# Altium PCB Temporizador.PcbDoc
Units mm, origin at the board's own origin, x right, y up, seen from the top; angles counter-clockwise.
Board outline 120.65 x 55.24 mm, 2 copper layers (Top Layer, Bottom Layer); 47 components, 35 nets, 161 pads, 9 vias.
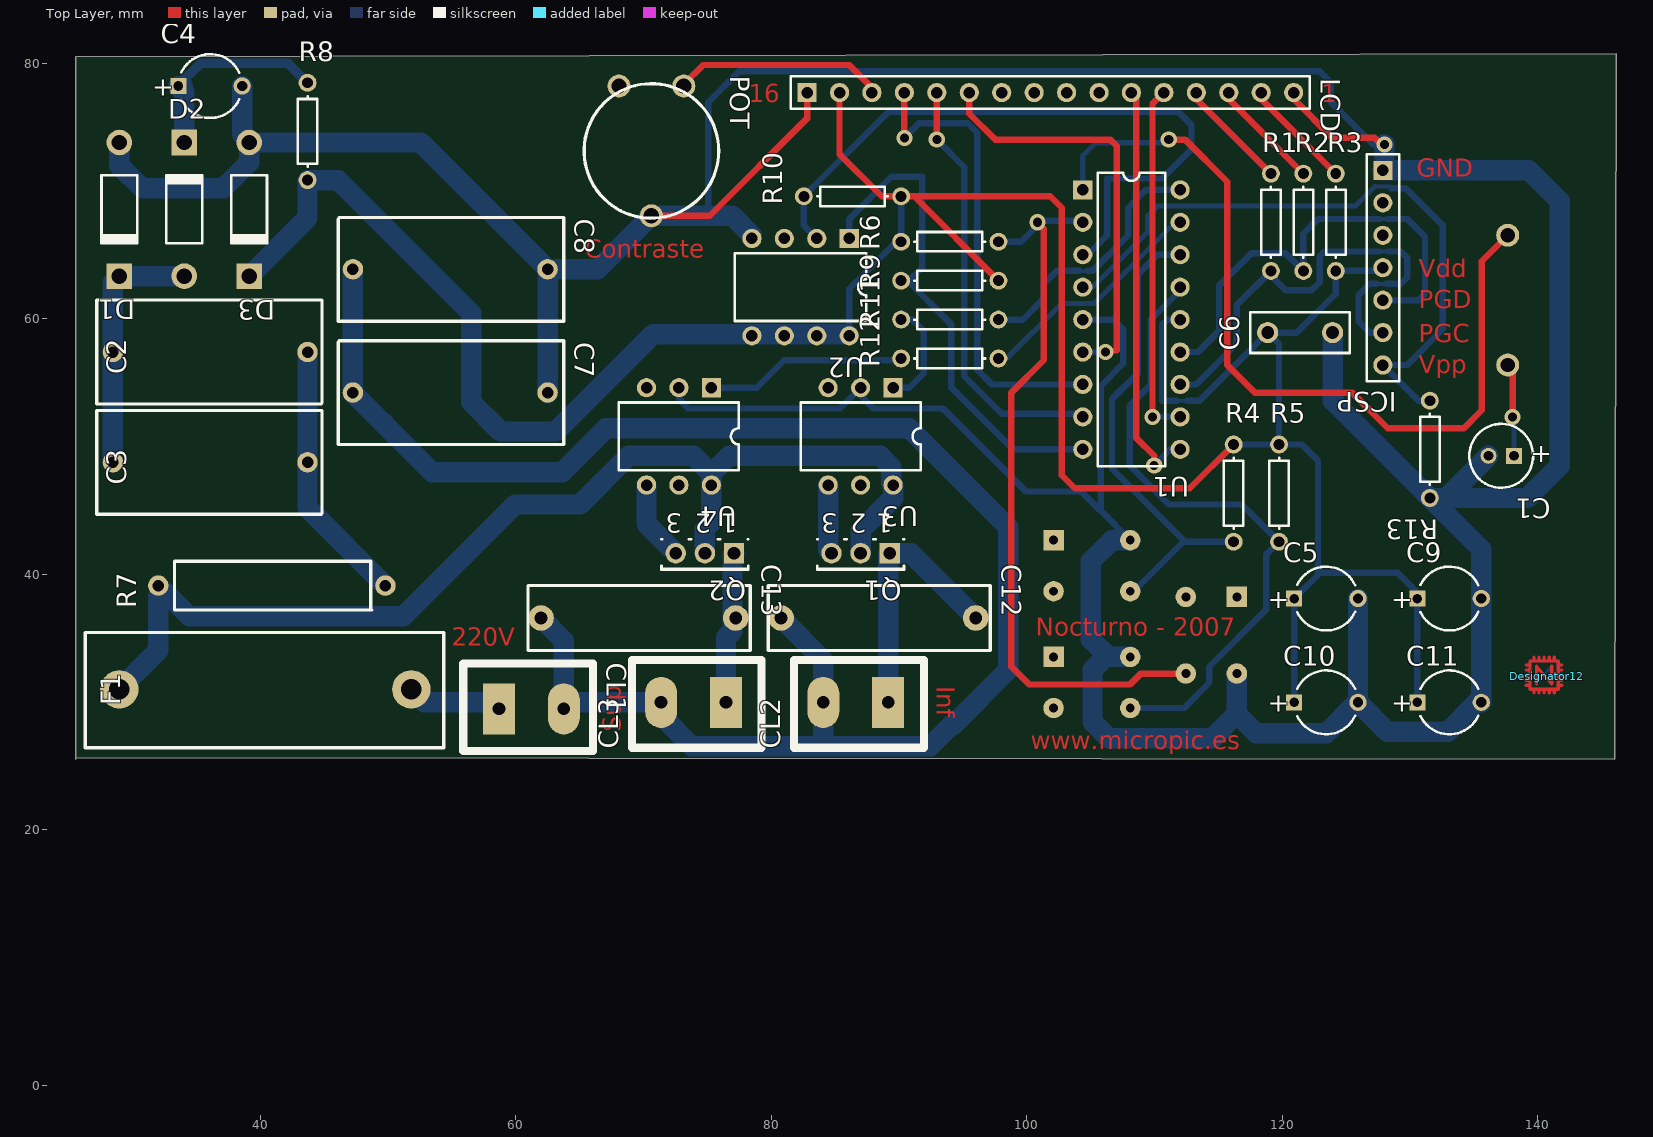
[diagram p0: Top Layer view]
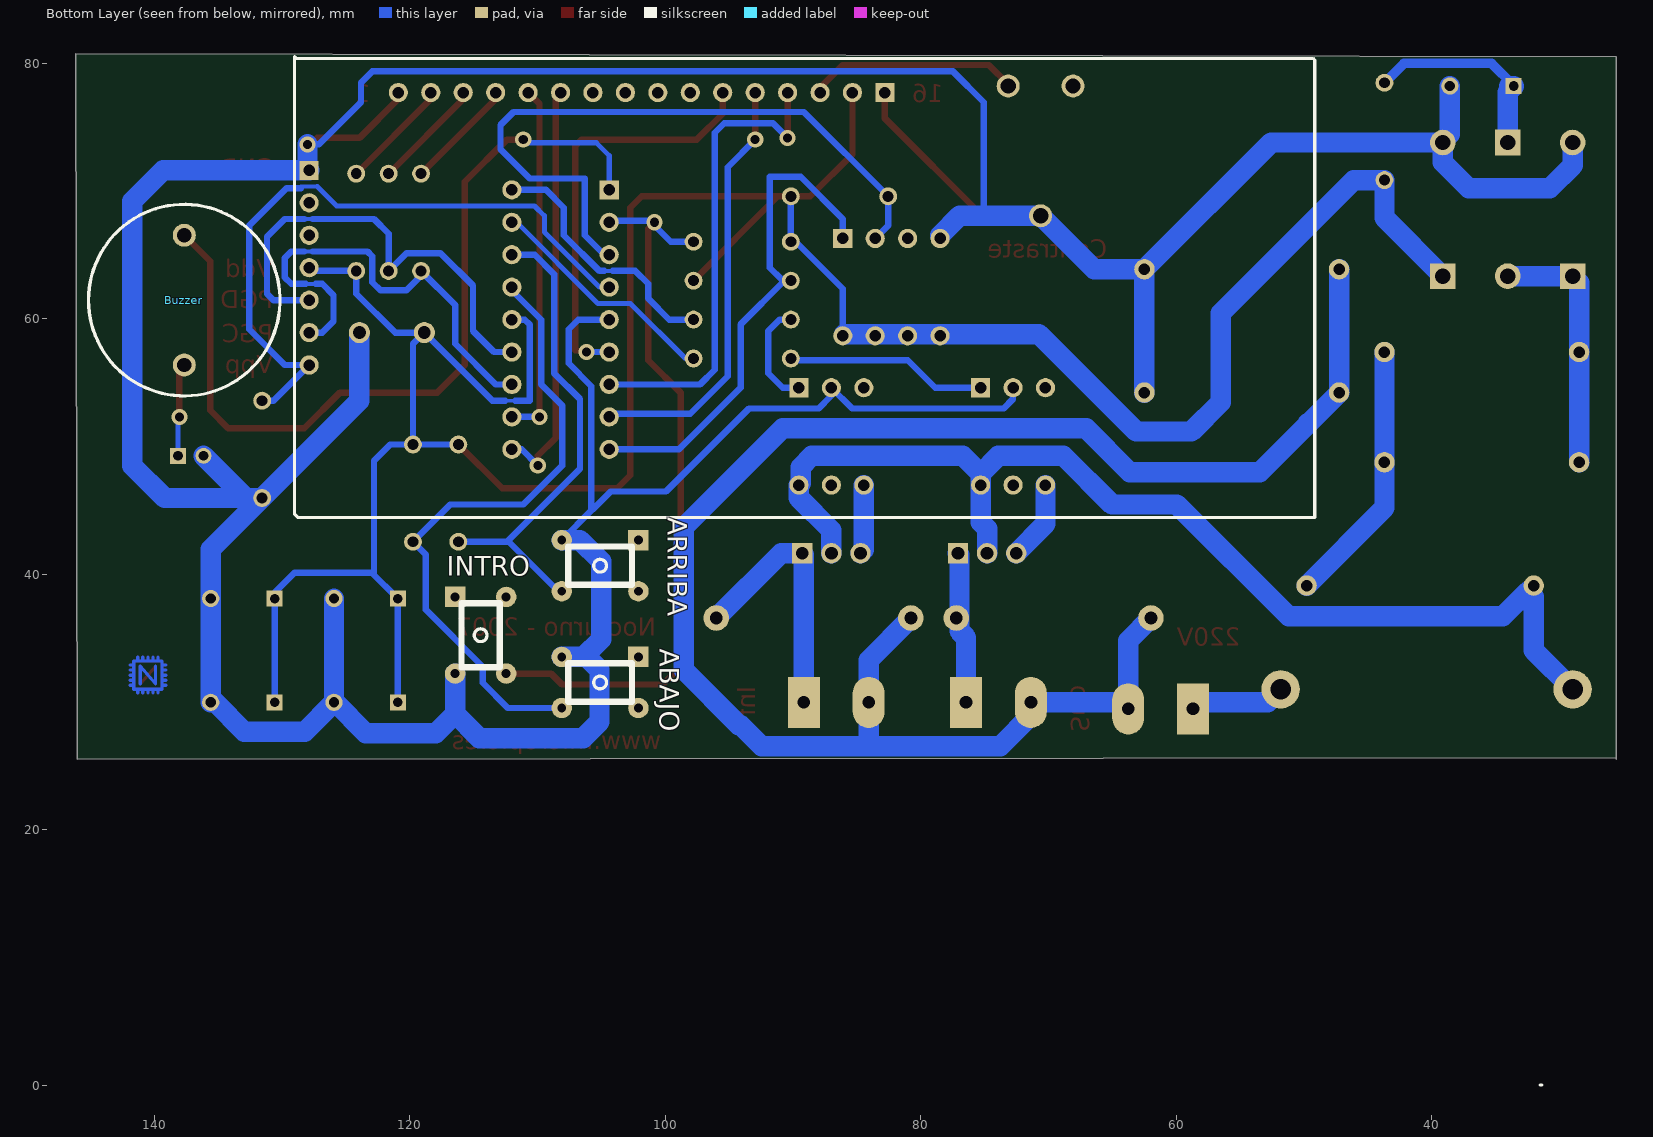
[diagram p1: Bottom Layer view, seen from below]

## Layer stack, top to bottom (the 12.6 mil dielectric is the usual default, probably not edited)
Top Layer: signal copper 0.0356
Dielectric: dielectric 0.32, FR-4, Dk 4.8
Bottom Layer: signal copper 0.0356

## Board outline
25.527,25.527 25.527,80.518 146.177,80.772 146.05,25.527 25.527,25.654

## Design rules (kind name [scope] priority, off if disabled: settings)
Clearance [InNet('220V_NEUTRO')] p1: gap=0.5
ComponentClearance [All] p1: gap=0.254 collisioncheckmode=3 verticalgap=0.254
PolygonConnect [All] p1: connectstyle=Relief reliefconductorwidth=0.254 reliefentries=4 polygonreliefangle="90 Angle"
RoutingLayers [All] p1: top layer_v5=FALSE bottom layer_v5=TRUE
RoutingVias [All] p1: holewidth=0.711 width=1.27 viastyle="Through Hole" minholewidth=0.711 minwidth=1.27 maxholewidth=0.711 maxwidth=1.27
SolderMaskExpansion [All] p1: expansion=0.102
TestPointUsage [All] p1: valid=0 allowmultiple=FALSE
Testpoint [All] p1: side=15 testpointundercomponent=TRUE minsize=1.016 maxsize=2.54 preferedsize=1.524 minholesize=0 maxholesize=1.016 preferedholesize=0.813 testpointgrid=0.025 style=1023 order=0123456789
Width [All] p1: maxlimit=1.6 minlimit=0.254 preferedwidth=0.254 toplayer_minwidth=0.5 toplayer_maxwidth=0.5 toplayer_prefwidth=0.5 bottomlayer_minwidth=0.3 bottomlayer_prefwidth=1.6 minimp=50.000000 maximp=50.000000 favimp=50.000000
17 further rules are at their usual default settings.

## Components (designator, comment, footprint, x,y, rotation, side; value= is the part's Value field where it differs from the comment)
ABAJO "SW-PB" pulsador 102.108,33.528 r270 bottom
ARRIBA "SW-PB" pulsador 102.108,42.672 r270 bottom
Buzzer "Buzzer" BUZZER 137.668,58.928 r90 bottom
C1 "Cap Pol1" B 137.16,49.276 r180 top
C2 "Cap" RAD-5 36.068,57.404 r180 top
C3 "Cap" RAD-5 36.068,48.768 r180 top
C4 "Cap Pol1" CAPPR5-5x5 36.068,78.232 r0 top
C5 "Cap Pol1" CAPPR5-5x5 123.444,38.1 r0 top
C6 "Cap" VP45-3.2 121.412,58.928 r180 top
C7 "Cap" RAD-5 54.864,54.229 r0 top
C8 "Cap" RAD-5 54.864,63.881 r0 top
C9 "Cap Pol1" CAPPR5-5x5 133.096,38.1 r0 top
C10 "Cap Pol1" CAPPR5-5x5 123.444,29.972 r0 top
C11 "Cap Pol1" CAPPR5-5x5 133.096,29.972 r0 top
C12 "Cap" COND56K 88.392,36.576 r0 top
C13 "Cap" COND56K 69.596,36.576 r0 top
CL1 "220V" Clema-2 54.864,29.464 r0 top
CL2 "Cara inferior" Clema-2 92.964,29.972 r180 top
CL3 "Cara superior" Clema-2 80.264,29.972 r180 top
D1 "Diode 1N4007" DO-41 28.956,68.58 r270 top
D2 "Diode 1N4007" DO-41 34.036,68.58 r90 top
D3 "5V1" do-41 39.116,68.58 r270 top
Designator12 "Comment" Firma 140.716,32.004 r0 top
F1 "Fuse 2" FUSE 36.576,30.988 r180 top
ICSP "Header 7" HDR1X7 127.889,71.628 r270 top
INTRO "SW-PB" pulsador 116.459,38.227 r180 bottom
LCD "Header 16" HDR1X16 82.804,77.724 r0 top
POT "RPot" POTENCIOMETRO 70.612,75.692 r270 top
Q1 "Triac" 369-03 86.995,41.656 r180 top
Q2 "Triac" 369-03 74.803,41.656 r180 top
R1 "Res1" AXIAL-0.3 119.126,67.564 r90 top
R2 "Res1" AXIAL-0.3 121.666,67.564 r90 top
R3 "Res1" AXIAL-0.3 124.206,67.564 r90 top
R4 "Res1" AXIAL-0.3 116.205,46.355 r90 top
R5 "Res1" AXIAL-0.3 119.761,46.355 r90 top
R6 "Res1" AXIAL-0.3 93.98,66.04 r180 top
R7 "Res1" RES1W 42.164,39.116 r180 top
R8 "Res1" AXIAL-0.3 43.688,74.676 r90 top
R9 "Res1" AXIAL-0.3 93.98,62.992 r180 top
R10 "Res1" AXIAL-0.3 86.36,69.596 r180 top
R11 "Res1" AXIAL-0.3 93.98,59.944 r180 top
R12 "Res1" AXIAL-0.3 93.98,56.896 r180 top
R13 "Res1" AXIAL-0.3 131.572,49.784 r270 top
U1 "PIC16F628-04/P" PDIP300-18 108.204,59.944 r270 top
U2 "DS1624" DIP-8 82.296,62.484 r180 top
U3 "Opto TRIAC" DIP-6 86.995,50.8 r180 top
U4 "Opto TRIAC" DIP-6 72.771,50.8 r180 top

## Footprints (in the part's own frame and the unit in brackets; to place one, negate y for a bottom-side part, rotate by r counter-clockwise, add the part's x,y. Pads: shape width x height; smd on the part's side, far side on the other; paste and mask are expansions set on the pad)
369-03 [mm] "TO, Thru-Hole, Vertical, Heatsink Mounted; 3 In-Line Leads; Pitch 2.28 mm"
  rect 1.6x1.6 hole 1: 1(-2.28,0)
  round 1.6 hole 1: 2(0,0) 3(2.28,0)
  silkscreen extent -3.4,-1.1 3.4,1.3
AXIAL-0.3 [mm] "Resistor; 2 Leads"
  round 1.4 hole 0.85: 1(-3.81,0) 2(3.81,0)
  silkscreen extent -2.77,-0.76 2.77,0.76
B [mm] "Capacitor, Electrolytic, Radial; Body 5 x 6.8 mm (Dia.xH typ); Pin Spacing 2 mm (typ)"
  rect 1.25x1.25 hole 0.75: 1(-1,0)
  round 1.25 hole 0.75: 2(1,0)
  silkscreen extent -2.5,-2.5 2.5,2.5
BUZZER [mm]
  round 1.8 hole 1.1: 1(-2.54,0) 2(7.62,0)
  silkscreen extent -4.96,-7.5 10.04,7.5
CAPPR5-5x5 [mm] "Capacitor, Electrolytic, Radial; Body 5 x 5 mm (Dia.xH typ); Pin Spacing 5 mm (typ)"
  rect 1.25x1.25 hole 0.75: 1(-2.5,0)
  round 1.35 hole 0.8: 2(2.5,0)
  silkscreen extent -2.26,-2.5 2.27,2.5
Clema-2 [mm]
  rect 2.5x4 hole 1: 1(3.81,0)
  oval 2.5x4 hole 1: 2(8.89,0)
  silkscreen extent 1.02,-3.3 11.18,3.56
COND56K [mm]
  round 2 hole 1: 1(7.62,0) 2(-7.62,0)
  silkscreen extent -8.64,-2.54 8.76,2.54
DIP-6 [mm] "DIP; 6 Leads; Row Spacing 7.62 mm; Pitch 2.54 mm"
  rect 1.5x1.5 hole 0.9: 1(-2.54,-3.81)
  round 1.5 hole 0.9: 2(0,-3.81) 3(2.54,-3.81) 4(2.54,3.81) 5(0,3.81) 6(-2.54,3.81)
  silkscreen extent -4.7,-2.65 4.7,2.65
DIP-8 [mm]
  rect 1.5x1.5 hole 0.9: 1(-3.81,-3.81)
  round 1.5 hole 0.9: 2(-1.27,-3.81) 3(1.27,-3.81) 4(3.81,-3.81) 5(3.81,3.81) 6(1.27,3.81) 7(-1.27,3.81) 8(-3.81,3.81)
  silkscreen extent -5.15,-2.65 5.15,2.65
DO-41 [mm] "Diode, Axial; Body 5.2 x 2.7 mm (LxDia. max), Lead Dia. 0.86 mm (max)"
  round 2 hole 1.2: 1(-5.23,0)
  rect 2x2 hole 1.2: 2(5.23,0)
  silkscreen extent -2.65,-1.41 2.75,1.4
do-41 [mm] "Diode, Axial; Body 5.2 x 2.7 mm (LxDia. max), Lead Dia. 0.86 mm (max)"
  round 2 hole 1.2: 1(-5.23,0)
  rect 2x2 hole 1.2: 2(5.23,0)
  silkscreen extent -2.65,-1.4 2.75,1.4
Firma [mm] "Firma"
  Top Layer lines w0.254: -1.6,-0.7 -1.3,-0.7 ; -1.6,-0.3 -1.3,-0.3 ; -1.6,0.1 -1.3,0.1 ; -1.6,0.5 -1.3,0.5 ; -1.6,0.9 -1.3,0.9 ; -1,-1.3 -1,-1 ; -1,1.2 -1,1.5 ; -0.8,-0.6 -0.8,0.8 0.4,-0.6 0.4,0.8 ; -0.6,-1.3 -0.6,-1 ; -0.6,1.2 -0.6,1.5 ; -0.2,-1.3 -0.2,-1 ; -0.2,1.2 -0.2,1.5 ; 0.2,-1.3 0.2,-1 ; 0.2,1.2 0.2,1.5 ; 0.6,-1.3 0.6,-1 ; 0.6,1.2 0.6,1.5 ; 0.9,-0.7 1.2,-0.7 ; 0.9,-0.3 1.2,-0.3 ; 0.9,0.1 1.2,0.1 ; 0.9,0.5 1.2,0.5 ; 0.9,0.9 1.2,0.9 ; -1.3,-1 -1.3,1.2 0.9,1.2 0.9,-1 -1.3,-1
  Bottom Layer lines w0.254: -1.6,-0.7 -1.3,-0.7 ; -1.6,-0.3 -1.3,-0.3 ; -1.6,0.1 -1.3,0.1 ; -1.6,0.5 -1.3,0.5 ; -1.6,0.9 -1.3,0.9 ; -1,-1.3 -1,-1 ; -1,1.2 -1,1.5 ; -0.8,0.8 -0.8,-0.6 0.4,0.8 0.4,-0.6 ; -0.6,-1.3 -0.6,-1 ; -0.6,1.2 -0.6,1.5 ; -0.2,-1.3 -0.2,-1 ; -0.2,1.2 -0.2,1.5 ; 0.2,-1.3 0.2,-1 ; 0.2,1.2 0.2,1.5 ; 0.6,-1.3 0.6,-1 ; 0.6,1.2 0.6,1.5 ; 0.9,-0.7 1.2,-0.7 ; 0.9,-0.3 1.2,-0.3 ; 0.9,0.1 1.2,0.1 ; 0.9,0.5 1.2,0.5 ; 0.9,0.9 1.2,0.9 ; -1.3,-1 0.9,-1 0.9,1.2 -1.3,1.2 -1.3,-1
FUSE [mm]
  round 3 hole 1.6: 1(-15.24,0) 2(7.62,0)
  silkscreen extent -17.78,-4.45 10.29,4.57
HDR1X7 [mm] "Connector; Header; 7 Position"
  rect 1.5x1.5 hole 0.9: 1(0,0)
  round 1.5 hole 0.9: 2(2.54,0) 3(5.08,0) 4(7.62,0) 5(10.16,0) 6(12.7,0) 7(15.24,0)
  silkscreen extent -1.27,-1.27 16.51,1.27
HDR1X16 [mm] "Connector; Header; 16 Position"
  rect 1.5x1.5 hole 0.9: 1(0,0)
  round 1.5 hole 0.9: 2(2.54,0) 3(5.08,0) 4(7.62,0) 5(10.16,0) 6(12.7,0) 7(15.24,0) 8(17.78,0) 9(20.32,0) 10(22.86,0) 11(25.4,0) 12(27.94,0) 13(30.48,0) 14(33.02,0) 15(35.56,0) 16(38.1,0)
  silkscreen extent -1.27,-1.27 39.37,1.27
PDIP300-18 [mm] "DIP, Plastic; 18 Leads; Row Spacing 7.62 mm; Pitch 2.54 mm"
  rect 1.5x1.5 hole 0.9: 1(-10.16,-3.81)
  round 1.5 hole 0.9: 2(-7.62,-3.81) 3(-5.08,-3.81) 4(-2.54,-3.81) 5(0,-3.81) 6(2.54,-3.81) 7(5.08,-3.81) 8(7.62,-3.81) 9(10.16,-3.81) 10(10.16,3.81) 11(7.62,3.81) 12(5.08,3.81) 13(2.54,3.81) 14(0,3.81) 15(-2.54,3.81) 16(-5.08,3.81) 17(-7.62,3.81) 18(-10.16,3.81)
  silkscreen extent -11.5,-2.65 11.5,2.65
POTENCIOMETRO [mm]
  round 1.8 hole 1.2: 1(-2.54,2.54) 2(-2.54,-2.54) 3(7.62,0)
  silkscreen extent -2.73,-5.26 7.81,5.27
pulsador [mm] "Pulsador doble circuito"
  rect 1.6x1.6 hole 0.7: 0(0,0)
  round 1.6 hole 0.7: 1(0,-6) 2(4,-6) 3(4,0)
  silkscreen extent 0.5,-5.5 3.5,-0.5
RAD-5 [mm]
  round 1.6 hole 0.9: 1(-7.62,0) 2(7.62,0)
  silkscreen extent -8.76,-4.06 8.89,4.06
RES1W [mm]
  round 1.6 hole 0.9: 1(-7.62,0) 2(10.16,0)
  silkscreen extent -6.55,-1.91 8.89,1.91
VP45-3.2 [mm] "Capacitor, Ceramic, Thru-Hole, Dipped Radial; Body 7.8 x 3.2 mm (WxT) Pin Spacing 5.08 mm (typ)"
  round 1.65 hole 1: 1(-2.54,0) 2(2.54,0)
  silkscreen extent -3.9,-1.6 3.9,1.6

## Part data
ABAJO ARRIBA INTRO: "Switch"
Buzzer: "Magnetic Transducer Buzzer"
C1 C4 C5 C9 C10 C11: "Polarized Capacitor (Radial)"
C2 C3 C6 C7 C8 C12 C13: "Capacitor"
CL1 CL2 CL3: library part Clema-2
D1 D2: "1 Amp General Purpose Rectifier"
D3: library part "D Zener", "Zener Diode"
F1: "Fuse"
ICSP: "Header, 7-Pin"
LCD: "Header, 16-Pin"
POT: "Potentiometer"
Q1 Q2: "Silicon Bidirectional Triode Thyristor"
R1 R2 R3 R4 R5 R6 R7 R8 R9 R10 R11 R12 R13: "Resistor"
U1: "FLASH-Based 8-Bit CMOS Microcontroller, 2K (x14-Bit words) FLASH, 224 Bytes RAM, 4 MHz, 18-Pin PDIP, 3.0 to 5.5V Supply Range, Commercial Temperature"
U3 U4: "Opto-Triac"

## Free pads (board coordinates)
  round 4.6 on Mech1: 0(28.702,41.021) 0(28.702,77.5) 0(140,41.021) 0(140,77.5)
  round 3.1 on Mech1: 0(51,46) 0(51,78) 0(127,46) 0(127,78)
  round 3.5 on Mech1: 0(105.156,31.496) 0(105.156,40.64) 0(114.427,35.306)

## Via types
v1: diameter 1.27, hole 0.711, Top Layer to Bottom Layer, 9 vias

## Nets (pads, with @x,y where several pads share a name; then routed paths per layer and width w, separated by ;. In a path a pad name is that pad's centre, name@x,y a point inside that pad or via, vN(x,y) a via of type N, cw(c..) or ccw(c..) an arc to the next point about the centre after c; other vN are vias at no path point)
220V_FASE: F1.2 Q1.2 Q2.2 R7.2 U3.6 U4.6 | length 87.9
  Bottom Layer w1.6: F1.2 32.004,34.036 32.004,38.227 32.448,38.672 34.417,36.703 51.181,36.703 59.944,45.466 65.024,45.466 68.834,49.276 73.914,49.276 75.311,47.879 ; Q2.2 74.803,43.561 75.311,44.069 75.311,47.879 ; Q1.2 86.995,43.434 89.535,45.974 U3.6 89.408,47.117 89.408,48.387 88.519,49.276 76.708,49.276 75.311,47.879
220V_NEUTRO: C7.1 C8.1 C12.2 C13.2 CL1.2 CL2.2 CL3.2 | length 138.1
  Bottom Layer w1.6: C8.1 C7.1 53.467,48.006 63.627,48.006 67.056,51.435 90.805,51.435 98.552,43.688 98.552,32.512 94.234,28.194 94.107,28.194 92.456,26.543 73.787,26.543 71.247,29.083 71.247,29.845 CL3.2 CL1.2@63.754,29.972 ; 49.679,51.794 49.701,51.816 ; C13.2 63.754,34.798 CL1.2 ; C12.2 84.074,33.274 84.074,26.67 84.201,26.543
GND: ABAJO.1 ARRIBA.1 C1.2 C4.2 C5.2 C6.1 C7.2 C8.2 C9.2 C10.2 C11.2 D1.1 D3.1 ICSP.1 INTRO.1 LCD.1 LCD.16 POT.3 R13.2 U1.5 U2.4 U3.2 U4.2 | length 381.7
  Top Layer w0.5: POT.3 75.184,68.072 82.804,75.692 LCD.1 ; LCD.16 120.904,77.216 123.952,74.168 127.254,74.168 127.762,73.66 v1(128.016,73.66)
  Bottom Layer w0.5: U4.2 72.771,53.721 73.507,52.985 85.37,52.985 U3.2 86.995,53.975 87.985,52.985 93.446,52.985 99.949,46.482 104.267,46.482 105.664,45.085 ; 75.057,68.072 75.057,76.962 77.47,79.375 122.936,79.375 123.825,78.486 123.825,76.962 127.127,73.66 v1(128.016,73.66) ; U1.5 106.807,59.944 107.569,59.182 107.569,56.515 105.791,54.737 105.791,44.989 ARRIBA.1
  Bottom Layer w1.6: D1.1 28.956,72.009 30.734,70.231 37.084,70.231 39.116,72.263 D3.1 ; C4.2 38.568,74.462 38.989,74.041 38.989,73.937 D3.1 ; C7.2 C8.2 ; U2.4@78.486,66.548 76.962,68.072 POT.3 66.421,63.881 C8.2 ; 106.426,33.528 105.029,34.925 105.029,41.021 106.68,42.672 ARRIBA.1 ; ABAJO.1 106.172,33.528 105.156,32.512 105.156,28.448 106.426,27.178 114.554,27.178 116.459,29.083 ; INTRO.1 116.459,29.083 ; C6.1 123.952,53.594 135.596,41.95 C11.2 135.255,29.972 132.969,27.686 128.23,27.686 C10.2 ; C5.2 C10.2 ; v1(128.016,73.66) 128.016,71.755 ICSP.1 139.319,71.628 141.732,69.215 141.732,48.514 139.192,45.974 R13.2 ; 132.858,45.974 C1.2 ; D3.1 52.555,73.81 C8.2 ; 116.459,29.083 117.983,27.559 123.444,27.559 125.857,29.972 C10.2
NetABAJO_2: ABAJO.2 R5.1 U1.15 | length 50.1
  Bottom Layer w0.5: ABAJO.2 112.332,29.528 114.3,31.496 114.3,32.766 118.745,37.211 118.745,41.529 R5.1 116.84,45.466 111.125,45.466 108.077,48.514 108.077,53.213 109.728,54.864 109.728,59.944 112.014,62.23 U1.15
NetARRIBA_2: ARRIBA.2 R4.1 U1.16 | length 37.8
  Bottom Layer w0.5: ARRIBA.2 108.395,38.672 112.268,42.545 R4.1 ; U1.16 110.236,65.024 108.712,63.5 108.712,55.753 106.68,53.721 106.68,48.26 112.395,42.545
NetBuzzer_1: Buzzer.1 C1.1 | length 7.3
  Top Layer w0.5: Buzzer.1 138.049,56.007 v1(138.049,52.324)
  Bottom Layer w0.4: v1(138.049,52.324) 138.16,52.213 C1.1
NetBuzzer_2: Buzzer.2 U1.1 | length 67.3
  Top Layer w0.5: v1(111.125,74.041) 112.395,74.041 115.697,70.739 115.697,56.388 117.856,54.229 125.476,54.229 128.27,51.435 134.239,51.435 135.636,52.832 135.636,64.516 Buzzer.2
  Bottom Layer w0.4: U1.1 104.394,72.771 105.41,73.787 110.871,73.787 v1(111.125,74.041)
NetC2_1: C2.1 C3.1 R7.1 | length 20.8
  Bottom Layer w1.6: C2.1 43.688,45.212 R7.1
NetC2_2: C2.2 C3.2 D1.2 D2.1 | length 19.9
  Bottom Layer w1.6: C3.2 C2.2 28.448,62.842 D1.2 D2.1
NetC4_1: C4.1 D2.2 R8.2 | length 16.5
  Bottom Layer w0.75: C4.1 33.568,78.272 35.306,80.01 42.164,80.01 R8.2
  Bottom Layer w1.6: C4.1@33.909,78.232 C4.1 34.036,77.764 D2.2
NetC12_1: C12.1 CL2.1 Q1.1 | length 20.6
  Bottom Layer w1.6: CL2.1 89.154,41.535 Q1.1 ; Q1.1@89.281,41.65 Q1.1 ; C12.1 90.932,41.656 Q1.1
NetC13_1: C13.1 CL3.1 Q2.1 | length 12
  Bottom Layer w1.6: CL3.1 76.454,35.052 76.962,35.56 76.962,41.535 Q2.1 Q2.1@77.089,41.65
NetCL1_1: CL1.1 F1.1 | length 7.3
  Bottom Layer w1.6: F1.1 52.832,29.972 CL1.1@58.674,29.972
NetICSP_5: ICSP.5 R2.1 U1.13 | length 37
  Bottom Layer w0.3: 127.611,67.818 128.27,67.818
  Bottom Layer w0.5: U1.13 113.411,57.404 115.062,59.055 115.062,62.611 117.602,65.151 120.269,65.151 R2.1 121.666,66.675 122.809,67.818 127.611,67.818 ; ICSP.5 130.683,61.468 131.191,61.976 131.191,66.421 129.794,67.818 128.27,67.818
NetICSP_6: ICSP.6 R1.1 U1.12 | length 37
  Bottom Layer w0.3: 127.381,62.738 128.167,62.738 ; 127.611,65.278 128.27,65.278
  Bottom Layer w0.5: U1.12 113.284,54.864 116.459,58.039 116.459,61.087 R1.1 119.126,63.373 120.269,62.23 122.301,62.23 122.936,62.865 122.936,64.897 123.317,65.278 127.611,65.278 ; 127.381,62.738 126.873,62.738 125.984,61.849 125.984,59.817 126.873,58.928 ICSP.6 ; 128.167,62.738 129.286,62.738 129.794,63.246 129.794,64.77 129.286,65.278 128.27,65.278
NetICSP_7: ICSP.7 R13.1 U1.4 | length 52.2
  Bottom Layer w0.3: 127.254,70.358 128.524,70.358
  Bottom Layer w0.4: U1.4 105.156,62.484 109.474,66.802 109.474,68.072 110.236,68.834 125.73,68.834 127.254,70.358
  Bottom Layer w0.5: 128.524,70.231 129.667,70.231 132.588,67.31 132.588,59.182 129.794,56.388 ICSP.7 130.683,53.594 R13.1
NetINTRO_2: INTRO.2 R6.1 U1.2 | length 58
  Top Layer w0.5: v1(100.838,67.564) 101.346,67.056 101.346,56.769 98.806,54.229 98.806,32.766 100.203,31.369 108.093,31.369 108.951,32.227 INTRO.2
  Bottom Layer w0.5: R6.1 99.568,66.04 101.219,67.691 104.267,67.691 U1.2
NetLCD_3: LCD.3 POT.1 | length 16.6
  Top Layer w0.5: POT.1 73.152,78.359 74.676,79.883 86.106,79.883 87.884,78.105 LCD.3
NetLCD_4: LCD.4 U1.7 | length 37.3
  Top Layer w0.5: v1(90.424,74.168) LCD.4
  Bottom Layer w0.5: v1(90.424,74.168) 91.567,75.311 95.377,75.311 96.123,74.565 96.123,56.023 97.282,54.864 U1.7
NetLCD_5: LCD.5 U1.8 | length 33.5
  Top Layer w0.5: v1(92.964,74.041) LCD.5
  Bottom Layer w0.5: v1(92.964,74.041) 95.123,71.882 95.123,55.499 98.044,52.578 U1.8@104.267,52.578
NetLCD_6: LCD.6 U1.6 | length 32.9
  Top Layer w0.5: LCD.6 95.504,76.073 97.536,74.041 106.553,74.041 107.061,73.533 107.061,57.531 v1(106.172,57.404)
  Bottom Layer w0.5: U1.6 v1(106.172,57.404)
NetLCD_11: LCD.11 U1.10 | length 32.5
  Top Layer w0.5: LCD.11 108.585,77.343 108.585,50.673 109.982,49.276 v1(109.982,48.514)
  Bottom Layer w0.5: v1(109.982,48.514) 111.252,49.784 U1.10
NetLCD_12: LCD.12 U1.11 | length 27.9
  Top Layer w0.5: v1(109.855,52.324) 109.855,76.835 LCD.12
  Bottom Layer w0.5: v1(109.855,52.324) U1.11
NetLCD_13: LCD.13 R1.2 | length 8.8
  Top Layer w0.5: LCD.13 113.284,77.216 R1.2
NetLCD_14: LCD.14 R2.2 | length 8.8
  Top Layer w0.5: LCD.14 115.824,77.216 R2.2
NetLCD_15: LCD.15 R3.2 | length 8.8
  Top Layer w0.5: LCD.15 118.364,77.216 R3.2
NetQ1_3: Q1.3 U3.4 | length 5.4
  Bottom Layer w1.6: U3.4 84.455,41.916 Q1.3
NetQ2_3: Q2.3 U4.4 | length 6.3
  Bottom Layer w1.6: U4.4 70.231,43.948 Q2.3
NetR11_1: R11.1 U1.18 | length 20.4
  Bottom Layer w0.3: 104.116,63.754 104.775,63.754
  Bottom Layer w0.5: R11.1 99.695,59.944 101.346,61.595 101.346,62.738 102.362,63.754 104.116,63.754 ; 104.775,63.754 105.156,63.754 107.95,66.548 107.95,68.707 109.347,70.104 U1.18
NetR11_2: R11.2 U3.1 | length 8.3
  Bottom Layer w0.5: U3.1 90.805,54.61 91.948,55.753 91.948,59.055 91.059,59.944 R11.2
NetR12_1: R12.1 U1.17 | length 18.6
  Bottom Layer w0.4: R12.1 98.425,56.896 102.743,61.214 105.283,61.214 111.633,67.564 U1.17
NetR12_2: R12.2 U4.1 | length 15.8
  Bottom Layer w0.5: U4.1 78.867,54.61 81.026,56.769 90.043,56.769 R12.2
SCL: R10.2 U1.3 U2.2 | length 53.7
  Bottom Layer w0.5: U2.2 82.55,67.31 R10.2 89.154,76.2 111.887,76.2 112.903,75.184 112.903,73.279 110.617,70.993 106.299,70.993 106.299,66.548 104.775,65.024 U1.3
SDA: R9.2 U1.9 U2.1 | length 40.4
  Bottom Layer w0.5: U2.1 86.106,67.818 89.408,71.12 91.821,71.12 91.821,64.008 90.932,63.119 90.297,63.119 R9.2 90.678,62.992 94.107,59.563 94.107,54.61 98.933,49.784 U1.9
VCC: C5.1 C6.2 C9.1 C10.1 C11.1 D3.2 ICSP.4 LCD.2 R3.1 R4.2 R5.2 R6.2 R8.1 R9.1 R10.1 U1.14 U2.5 U2.6 U2.7 U2.8 | length 232.8
  Top Layer w0.5: LCD.2 85.344,72.898 88.646,69.596 101.854,69.596 102.743,68.707 102.743,47.752 103.759,46.736 112.776,46.736 R4.2 ; 91.186,69.596 R9.1
  Bottom Layer w0.3: 111.736,53.594 112.522,53.594
  Bottom Layer w0.5: U2.8 85.979,58.801 86.106,58.928 86.106,62.357 89.789,66.04 R6.2 R10.1 ; 111.736,53.594 110.617,53.594 110.617,59.563 110.998,59.944 U1.14 ; 112.522,53.594 113.538,53.594 C6.2 ; R4.2 121.539,50.165 122.809,48.895 122.809,39.965 ; R5.2 119.761,58.039 C6.2 ; C10.1 C5.1 122.976,40.132 129.032,40.132 130.596,38.568 C11.1 ; ICSP.4 127.635,63.754 R3.1 124.206,61.976 121.158,58.928 C6.2
  Bottom Layer w1.6: D3.2 43.688,67.922 R8.1 46.101,70.866 56.515,60.452 56.515,53.467 58.801,51.181 63.119,51.181 70.739,58.801 U2.8@85.979,58.801
pads on no net: ABAJO.0 ABAJO.3 ARRIBA.0 ARRIBA.3 ICSP.2 ICSP.3 INTRO.0 INTRO.3 LCD.7 LCD.8 LCD.9 LCD.10 POT.2 U2.3 U3.3 U3.5 U4.3 U4.5

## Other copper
Top Layer:
  text "16" at 78.232,76.962 h1.4
  text "1" at 123.063,76.962 h1.4
  text "GND" at 130.556,71.12 h1.4
  text "Contraste" at 65.405,64.77 h1.4
  text "Vdd" at 130.683,63.246 h1.4
  text "PGD" at 130.683,60.833 h1.4
  text "PGC" at 130.683,58.166 h1.4
  text "Vpp" at 130.683,55.753 h1.4
  text "Nocturno - 2007" at 100.711,35.179 h1.4
  text "220V" at 54.991,34.417 h1.4
  text "Inf" at 92.964,31.242 h1.4 r270
  text "Sup" at 68.199,27.686 h1.4 r90
  text "www.micropic.es" at 100.33,26.289 h1.4

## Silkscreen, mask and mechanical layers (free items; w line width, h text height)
Bottom Overlay:
  lines w0.254: 31.369,0 31.496,0 ; 49.149,44.45 49.149,80.264 49.276,80.391 128.905,80.391 129.032,80.518 129.032,44.704 128.778,44.45 49.149,44.45
Mechanical 1:
  lines w0.254: 25.527,80.391 25.527,25.527 25.4,25.4 146.177,25.4 146.177,80.645 146.05,80.772 25.654,80.772 25.527,80.645 ; 52.922,50 125,50 125,75.391 52.922,75.391 52.922,50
